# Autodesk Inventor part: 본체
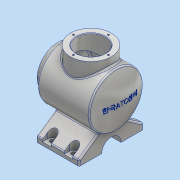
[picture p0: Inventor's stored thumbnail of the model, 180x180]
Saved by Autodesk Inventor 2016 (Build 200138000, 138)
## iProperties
Created: 2017-04
Part Number: 본체
Material: 알루미늄 6061
Document SubType Name: Modeling
Designer: 201-06
Density: 2.7 g/cm^3
Appearance: 알루미늄 - 평지
Mass: 1664.55 g
Surface Area: 1066.84 cm^2
Volume: 616.5 cm^3
Author: 201-06
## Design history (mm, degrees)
sketch "스케치1"
  geometry: L1 (62, 82)-(62, 120); L2 (0, 147)-(-38, 147); L3 (-38, 147)-(-38, 96.947); L4 (-38, 96.947)-(0, 96.947); L5 (0, 96.947)-(0, 147); L6 (53, 120)-(62, 120); L7 (62, 120)-(62, 82); L8 (62, 82)-(-58, 82); L9 (47, 132)-(-44.454, 132); L10 (50, 123)-(50, 129); A1 r 113 centre (55, 82) between (-47.166, 130.282) and (-58, 82); A2 r 3 centre (53, 123) between (50, 123) and (53, 120); A3 r 3 centre (47, 129) between (50, 129) and (47, 132); A4 r 3 centre (-44.454, 129) between (-44.454, 132) and (-47.166, 130.282); 3 further points
  constraints: 20 end point, 9 point on circle, 6 tangent, 4 centre point, 2 equal radius, 2 horizontal, 2 parallel, 2 perpendicular, 1 point on line, 1 vertical alignment
  dimensions: "d1" = 82 vertical distance of point (0, 0) L8.end; "d2" = 147 distance from line of point (0, 0) L2; "d3" = 38 distance of L2.start L2.end; "d9" = 3 radius of A2; "d97" = 12 distance between parallel lines of L10 L1; "d98" = 50 distance from line of L10 L2.start; "d102" = 108 distance from line of L8.end L10
revolve "회전1" stored, may be unused: angle "d10" = 90 deg
revolve "회전2" stored, may be unused: angle "d11" = 90 deg
node "작업 평면1"
node "작업 평면3"
sketch "스케치10"
  geometry: L1 (-82, 60)-(-82, 18); L2 (-82, -18)-(-82, -60); L3 (-72, 60)-(-29.988, 0); L4 (-72, -60)-(-29.988, 0); L5 (-82, -60)-(-72, -60); L6 (-82, 60)-(-72, 60); A1 r 18 centre (-82, 0) between (-82, -18) and (-82, 18); 2 further points
  constraints: 12 end point, 2 point on circle, 1 centre point, 1 coincident, 1 horizontal, 1 parallel
  dimensions: "d114" = 10 distance of L2.end L4.start
extrude "돌출3" join sketch "스케치10" distance "d105" = 80; taper "d106" = 0 deg
sketch "스케치3"
  geometry: L1 (-30, 60)-(-30, 50); L2 (-14, 60)-(-14, 50); L3 (10, 50)-(10, 60); L4 (26, 50)-(26, 60); L5 (-30, -60)-(-30, -50); L6 (-14, -60)-(-14, -50); L7 (10, -50)-(10, -60); L8 (26, -50)-(26, -60); L9 (-30, 60)-(-14, 60); L10 (10, 60)-(26, 60); L11 (26, -60)-(10, -60); L12 (-14, -60)-(-30, -60); A1 r 8 centre (-22, 50) between (-30, 50) and (-14, 50); A2 r 8 centre (18, 50) between (10, 50) and (26, 50); A3 r 8 centre (18, -50) between (26, -50) and (10, -50); A4 r 8 centre (-22, -50) between (-14, -50) and (-30, -50); 2 further points
  constraints: 24 end point, 8 point on circle, 4 centre point
extrude "돌출2" cut sketch "스케치3" stored distance "d37" = 80; taper "d38" = 0 deg
sketch "스케치4"
  geometry: L1 (-42, 60)-(38, 60) reference; L2 (-42, 18)-(-42, 60) reference; 4 further points
hole "구멍1" sketch "스케치4" at (-22, 50), (18, 50), (18, -50), (-22, -50) diameter "d43" = 8; stored, may be unused: countersink angle "d47" = 90 deg, drill point angle "d49" = 118 deg; dims "d44" = 6, "d45" = 4, "d46" = 2, "d48" = 8
sketch "스케치5"
  geometry: L1 (38, 147)-(-38, 147) reference; L2 (0, 147)-(-27, 147); L3 (-27, 147)-(-27, 88.38); L4 (-27, 88.38)-(0, 88.38); L5 (0, 88.38)-(0, 147); 1 further point
  constraints: 8 end point, 2 parallel, 1 horizontal, 1 midpoint, 1 perpendicular
  dimensions: "d50" = 27 distance of L4.end L3.end
revolve "회전3" sketch "스케치5" stored, may be unused: angle "d51" = 90 deg
sketch "스케치6"
  geometry: L1 (-37.903, 122)-(37, 122); L2 (-48, 82)-(62, 82); L3 (-48, 109)-(-44.398, 109); L4 (40, 109)-(62, 109); L5 (40, 109)-(40, 119); L6 (62, 109)-(62, 82); L7 (50, 35)-(50, 129) reference; L8 (-44.454, 132)-(47, 132) reference; A1 r 103 centre (55, 82) between (-40.69, 120.11) and (-48, 82); A2 r 3 centre (37, 119) between (40, 119) and (37, 122); A3 r 3 centre (-37.903, 45) between (-40.69, 43.89) and (-37.903, 42); A4 r 3 centre (-37.903, 119) between (-37.903, 122) and (-40.69, 120.11); A5 r 113 centre (55, 82) between (-47.166, 130.282) and (-47.166, 33.718) reference; 1 further point
  constraints: 12 end point, 9 point on circle, 5 tangent, 4 centre point, 2 parallel, 1 horizontal, 1 perpendicular
  dimensions: "d56" = 3 radius of A2; "d99" = 10 distance between parallel lines of L1 L8; "d100" = 10 distance between parallel lines of L7 L5; "d101" = 10 radial gap between concentric circles of A5 A1
revolve "회전4" sketch "스케치6" stored, may be unused: angle "d58" = 90 deg
chamfer "모따기1" distance "d59" = 1; stored, may be unused: second distance "d60" = 2, angle "d61" = 45 deg
fillet "모깎기1" dims "d62" = 3
chamfer "모따기2" distance "d66" = 1; stored, may be unused: second distance "d67" = 2, angle "d68" = 45 deg
sketch "스케치7"
  geometry: 5 further points
  constraints: 5 other
  dimensions: "d72" = 360 deg dimension on point (0, 0) point (0, -32.5) (derived)
sketch "스케치8"
  geometry: 6 further points
  constraints: 5 other
  dimensions: "d77" = 360 deg dimension on point (0, 0) point (0, 32.5) (derived)
hole "구멍2" sketch "스케치7" diameter "d79" = 3.242; stored, may be unused: countersink angle "d83" = 90 deg, drill point angle "d85" = 118 deg; dims "d80" = 8, "d81" = 4, "d82" = 2, "d84" = 10
hole "구멍3" sketch "스케치8" diameter "d86" = 3.242; stored, may be unused: countersink angle "d90" = 90 deg, drill point angle "d92" = 118 deg; dims "d87" = 8, "d88" = 4, "d89" = 2, "d91" = 10
node "작업 평면2"
sketch "스케치9"
  geometry: L1 (-33.183, 86.803)-(33.183, 86.803); L2 (33.183, 86.803)-(33.183, 77.197); L3 (33.183, 77.197)-(-33.183, 77.197); L4 (-33.183, 77.197)-(-33.183, 86.803); C1 r 48.282 at (0, 82) reference; 2 further points
  constraints: 2 other
feature "엠보싱1" sketch "스케치9" dims "d1" = 82, "d2" = 147, "d3" = 38, "d9" = 3, "d94" = 0.5, "d95" = 0, "d97" = 12, "d98" = 50, "d102" = 108
fillet "모깎기5" dims "d107" = 3, "d115" = 2
fillet "모깎기6" dims "d108" = 3
node "솔리드1"
other parameters: "d18" = 6, "d31" = 10, "d57" = 27, "d103" = -8
